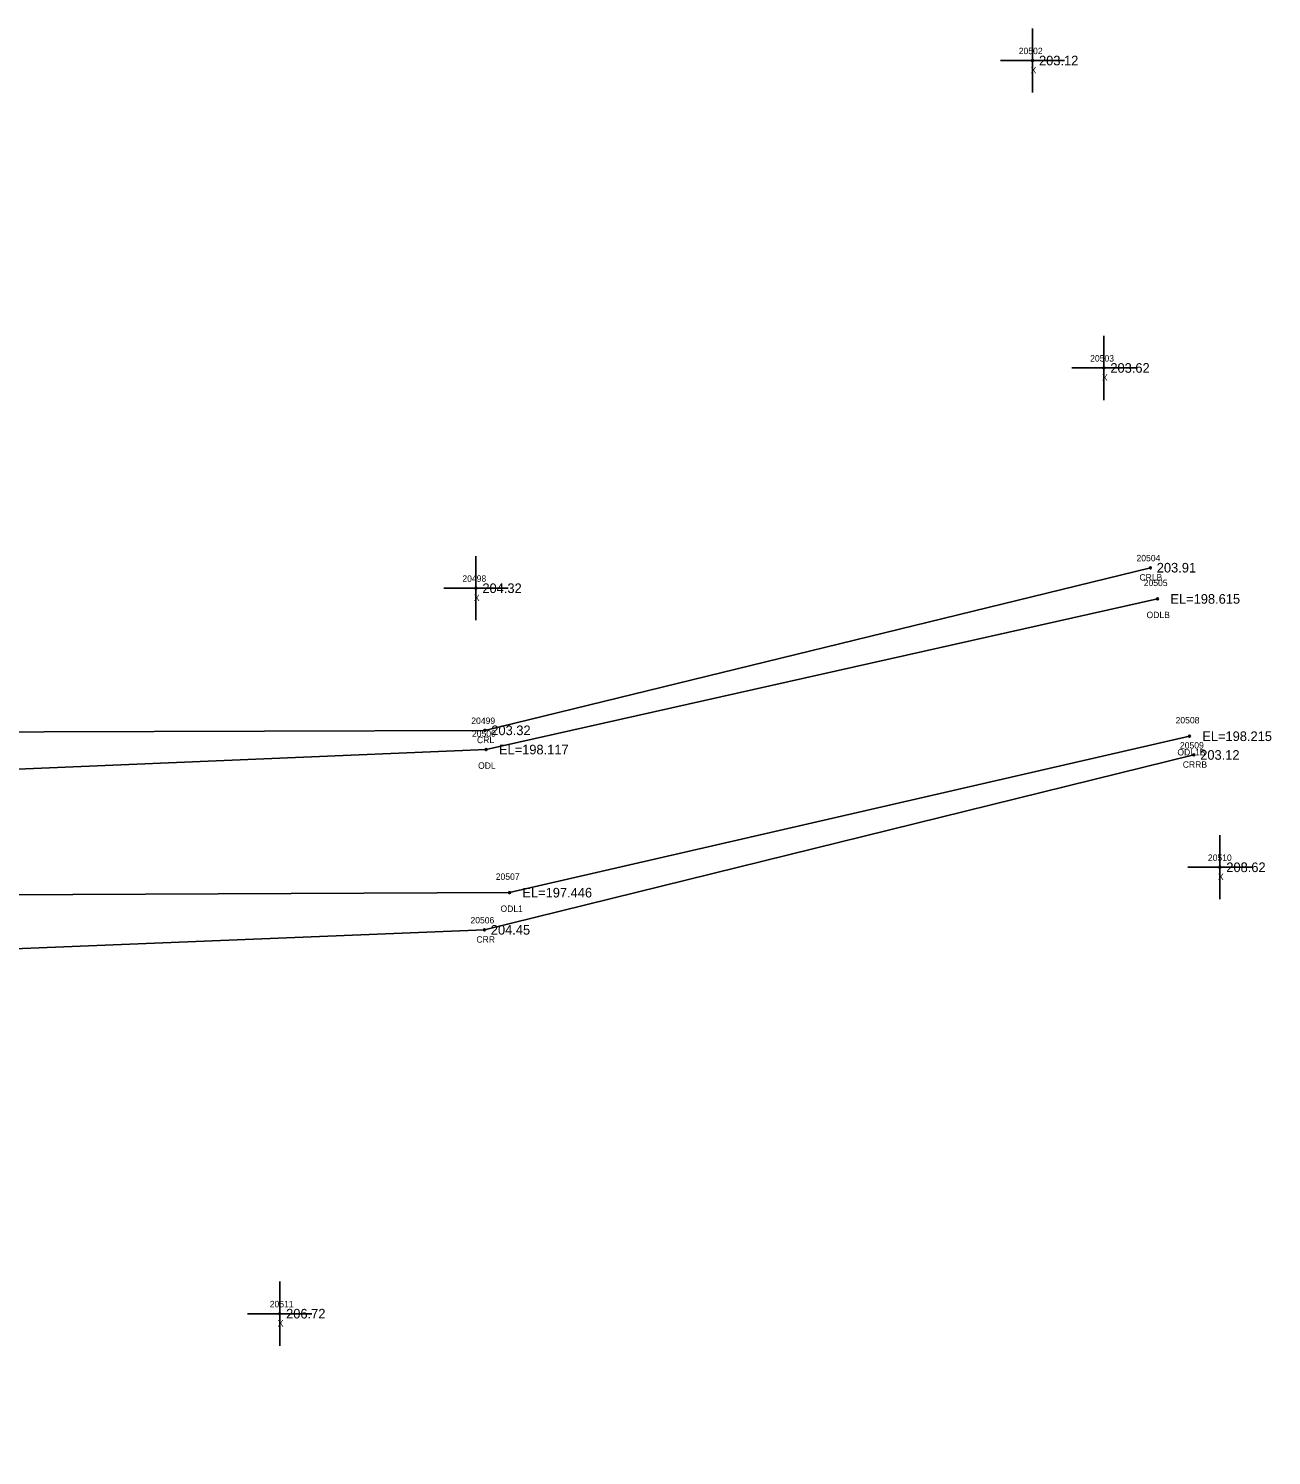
# Model space of a CAD drawing. Extents: x 2260230 to 2261304, y 1064626 to 1065587.
# Drawn here: x 2261110.1 to 2261304, y 1065075.6 to 1065298.3 of the extents above; entities that cross this region are included whole.
import ezdxf

# ---------------------------------------------------------------- set-up
doc = ezdxf.new("R2010")
doc.units = 0
for name, color, linetype in [('RD_EX_H2O', 7, 'Continuous'), ('RD_EX_H2O_txCode', 7, 'Continuous'), ('RD_EX_Misc', 7, 'Continuous'), ('RD_EX_Misc_txCode', 7, 'Continuous'), ('RD_EX_TX_H2O_ELEV', 7, 'Continuous'), ('RD_EX_TX_Misc_ELEV', 7, 'Continuous'), ('RD_SMD_Locator', 7, 'Continuous')]:
    doc.layers.add(name, color=color, linetype=linetype)

msp = doc.modelspace()

# ---------------------------------------------------------------- linework, layer by layer
at = {"layer": 'RD_EX_H2O'}
for points in [[(2260885.41, 1065184.64), (2260936, 1065235.25), (2260958.14, 1065240.42), (2260996.14, 1065264.19), (2261041.44, 1065253.62), (2261057.19, 1065228.35), (2261051.93, 1065209.3), (2261057.29, 1065196.01), (2261078.07, 1065188.45), (2261181.25, 1065188.78), (2261285.07, 1065214.16)], [(2260772.5, 1065076.18), (2260808.2, 1065117.04), (2260848.54, 1065142.46), (2260881.52, 1065170.81), (2260885.55, 1065179.82), (2260940.26, 1065230.7), (2260962.59, 1065234.94), (2260997.55, 1065261.89), (2261039.02, 1065251.85), (2261039.02, 1065251.85), (2261052.94, 1065229.55), (2261043.13, 1065204.67), (2261054.65, 1065194.09), (2261077.36, 1065181.43), (2261181.44, 1065185.78), (2261286.2, 1065209.29)], [(2260798.69, 1065050.24), (2260824.47, 1065095.61), (2260899.49, 1065151.99), (2260934.71, 1065184.11), (2260972.92, 1065212.25), (2260990.72, 1065208.66), (2261010.85, 1065196.45), (2261038.36, 1065172.55), (2261071.49, 1065162.95), (2261185.1, 1065163.45), (2261291.17, 1065187.86)], [(2260835.04, 1065077.78), (2260839.45, 1065081.34), (2260836.25, 1065093.94), (2260905.11, 1065142.54), (2260939.15, 1065178.33), (2260943.42, 1065185.77), (2260976.49, 1065206.39), (2260992.26, 1065206.09), (2261009.06, 1065194.12), (2261027.03, 1065166.48), (2261074.3, 1065153.35), (2261181.18, 1065157.65), (2261291.85, 1065184.94)]]:
    msp.add_lwpolyline(points, dxfattribs=at)
at = {"layer": 'RD_EX_Misc'}
for p, q in [((2261266.7, 1065288.3), (2261266.7, 1065298.3)), ((2261261.7, 1065293.3), (2261271.7, 1065293.3)), ((2261277.83, 1065240.33), (2261277.83, 1065250.33)), ((2261272.83, 1065245.33), (2261282.83, 1065245.33)), ((2261179.86, 1065205.96), (2261179.86, 1065215.96)), ((2261174.86, 1065210.96), (2261184.86, 1065210.96)), ((2261295.92, 1065162.41), (2261295.92, 1065172.41)), ((2261290.92, 1065167.41), (2261300.92, 1065167.41)), ((2261149.24, 1065092.75), (2261149.24, 1065102.75)), ((2261144.24, 1065097.75), (2261154.24, 1065097.75))]:
    msp.add_line(p, q, dxfattribs=at)
at = {"layer": 'RD_SMD_Locator'}
for centre in [(2261266.7, 1065293.3), (2261277.83, 1065245.33), (2261285.07, 1065214.16), (2261179.86, 1065210.96), (2261286.2, 1065209.29), (2261181.25, 1065188.78), (2261291.17, 1065187.86), (2261181.44, 1065185.78), (2261291.85, 1065184.94), (2261295.92, 1065167.41), (2261185.1, 1065163.45), (2261181.18, 1065157.65), (2261149.24, 1065097.75)]:
    msp.add_circle(centre, 0.15, dxfattribs=at)

# ---------------------------------------------------------------- texts
at = {"layer": 'RD_EX_H2O_txCode'}
for s, p in [('20504', (2261282.91, 1065215.16)), ('CRLB', (2261283.37, 1065212.16)), ('20505', (2261284.04, 1065211.29)), ('ODLB', (2261284.48, 1065206.29)), ('20499', (2261179.13, 1065189.78)), ('20508', (2261289.01, 1065189.86)), ('20500', (2261179.24, 1065187.78)), ('CRL', (2261180.02, 1065186.78)), ('ODL1B', (2261289.29, 1065184.86)), ('20509', (2261289.69, 1065185.94)), ('ODL', (2261180.19, 1065182.78)), ('CRRB', (2261290.13, 1065182.94)), ('20507', (2261182.95, 1065165.45)), ('ODL1', (2261183.69, 1065160.45)), ('20506', (2261179, 1065158.65)), ('CRR', (2261179.93, 1065155.65))]:
    msp.add_text(s, height=1, dxfattribs=at).set_placement(p)
at = {"layer": 'RD_EX_Misc_txCode'}
for s, p in [('20502', (2261264.54, 1065294.3)), ('X', (2261266.39, 1065291.3)), ('20503', (2261275.68, 1065246.33)), ('X', (2261277.52, 1065243.33)), ('20498', (2261177.74, 1065211.96)), ('X', (2261179.54, 1065208.96)), ('20510', (2261294.05, 1065168.41)), ('X', (2261295.61, 1065165.41)), ('20511', (2261147.69, 1065098.75)), ('X', (2261148.93, 1065095.75))]:
    msp.add_text(s, height=1, dxfattribs=at).set_placement(p)
at = {"layer": 'RD_EX_TX_H2O_ELEV'}
for s, p in [('203.91', (2261286.07, 1065213.41)), ('EL=198.615', (2261288.2, 1065208.54)), ('203.32', (2261182.25, 1065188.03)), ('EL=198.215', (2261293.17, 1065187.11)), ('EL=198.117', (2261183.44, 1065185.03)), ('203.12', (2261292.85, 1065184.19)), ('EL=197.446', (2261187.1, 1065162.7)), ('204.45', (2261182.18, 1065156.9))]:
    msp.add_text(s, height=1.5, dxfattribs=at).set_placement(p)
at = {"layer": 'RD_EX_TX_Misc_ELEV'}
for s, p in [('203.12', (2261267.7, 1065292.55)), ('203.62', (2261278.83, 1065244.58)), ('204.32', (2261180.86, 1065210.21)), ('208.62', (2261296.92, 1065166.66)), ('206.72', (2261150.24, 1065097))]:
    msp.add_text(s, height=1.5, dxfattribs=at).set_placement(p)

doc.saveas('drawing.dxf')
